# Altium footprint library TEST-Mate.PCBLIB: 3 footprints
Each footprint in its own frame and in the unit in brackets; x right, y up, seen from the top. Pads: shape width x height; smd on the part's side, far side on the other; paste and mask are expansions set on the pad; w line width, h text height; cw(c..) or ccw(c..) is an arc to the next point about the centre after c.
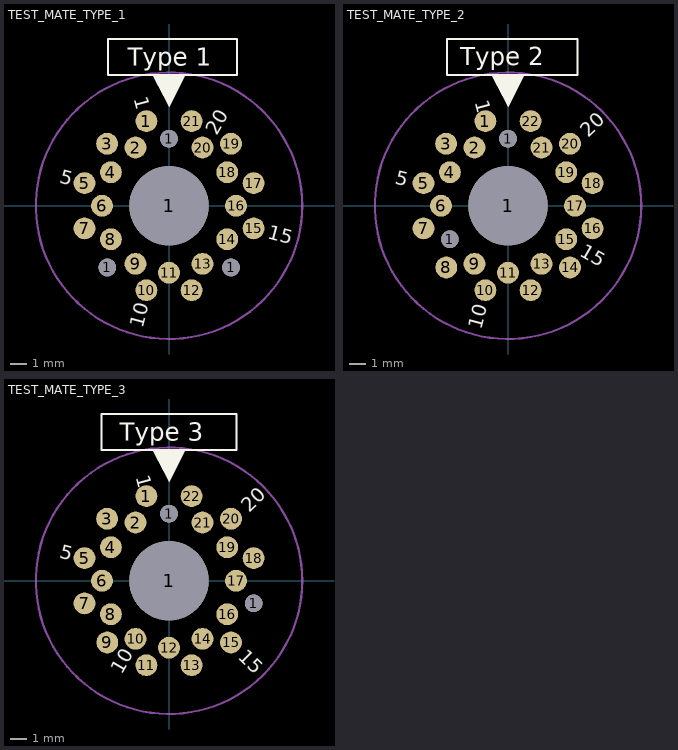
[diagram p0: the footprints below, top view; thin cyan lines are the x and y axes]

## TEST_MATE_TYPE_1 [mil]
pads (25):
  round 42 hole 42 unplated: 1(-147.24,-147.24) 1(0,160) 1(148,-147.24)
  rrect100% 52x52 smd: 1(-53.94,202) 2(-79.92,139) 3(-147.64,148) 4(-138.58,80) 5(-201.57,54) 6(-159.84,0) 7(-201.57,-53.94) 8(-138.58,-79.92) 9(-79.92,-138.58) 10(-53.94,-201.57) 11(0,-159.84) 12(54,-201.57) 13(80,-138.58) 14(139,-79.92) 15(202,-53.94) 16(160,0) 17(202,54) 18(139,80) 19(148,148) 20(80,139) 21(54,202)
  round 189 hole 189 unplated: 1(0,0)
Top Overlay:
  region: -39.37,312 0,236.22 39.37,312
  lines w5: -145.67,312 -145.67,398 162,398 162,312 -145.67,312
  text "Type 1" at -98.43,334.65 h42.5
  text "15" at 232.77,-77.9 h34
  text "20" at 114.03,166.01 h34
  text "10" at -63.19,-293.77 h34
  text "5" at -263.35,55.04 h34
  text "1" at -84.01,255.59 h34
Mechanical 27:
  circle w5: c0,0 r318

## TEST_MATE_TYPE_2 [mil]
pads (25):
  round 42 hole 42 unplated: 1(-138.58,-79.92) 1(0,160)
  rrect100% 52x52 smd: 1(-53.94,202) 2(-79.92,139) 3(-147.64,148) 4(-138.58,80) 5(-201.57,54) 6(-159.84,0) 7(-201.57,-53.94) 8(-147.24,-147.24) 9(-79.92,-138.58) 10(-53.94,-201.57) 11(0,-159.84) 12(54,-201.57) 13(80,-138.58) 14(148,-147.24) 15(139,-79.92) 16(202,-53.94) 17(160,0) 18(202,54) 19(139,80) 20(148,148) 21(80,139) 22(54,202)
  round 189 hole 189 unplated: 1(0,0)
Top Overlay:
  region: -39.37,312 0,236.22 39.37,312
  lines w5: -145.67,312 -145.67,398 166,398 166,312 -145.67,312
  text "20" at 192,161 h34
  text "Type 2" at -114.17,335 h42.5
  text "10" at -63.25,-296.9 h34
  text "15" at 169.29,-118.11 h34
  text "5" at -271.29,52.31 h34
  text "1" at -79.67,247.31 h34
Mechanical 27:
  circle w5: c0,0 r318

## TEST_MATE_TYPE_3 [mil]
pads (25):
  rrect100% 52x52 smd: 1(-53.94,202) 2(-79.92,139) 3(-147.64,148) 4(-138.58,80) 5(-201.57,54) 6(-159.84,0) 7(-201.57,-53.94) 8(-138.58,-79.92) 9(-147.24,-147.24) 10(-79.92,-138.58) 11(-53.94,-201.57) 12(0,-159.84) 13(54,-201.57) 14(80,-138.58) 15(148,-147.24) 16(139,-79.92) 17(160,0) 18(202,54) 19(139,80) 20(148,148) 21(80,139) 22(54,202)
  round 189 hole 189 unplated: 1(0,0)
  round 42 hole 42 unplated: 1(0,160) 1(202,-53.94)
Top Overlay:
  region: -39.37,312 0,236.22 39.37,312
  lines w5: -161.42,312 -161.42,398 161,398 161,312 -161.42,312
  text "20" at 192,161 h34
  text "1" at -79.67,247.31 h34
  text "Type 3" at -118.11,334.65 h42.5
  text "15" at 162.63,-183.85 h34
  text "5" at -263.35,55.04 h34
  text "10" at -112.35,-226.09 h34
Mechanical 27:
  circle w5: c0,0 r318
